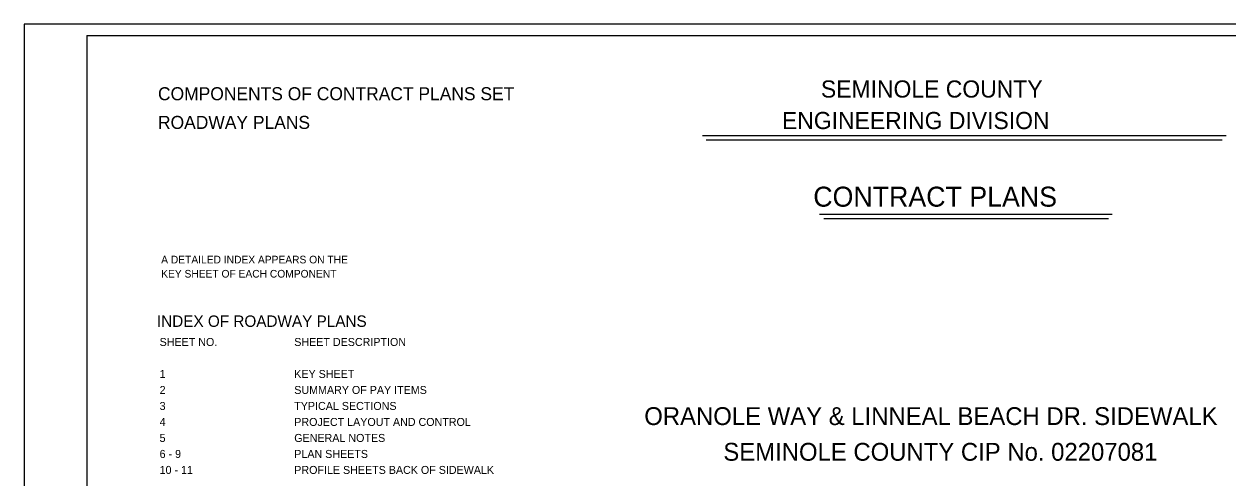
# Model space of a CAD drawing. Extents: x 2157516 to 2331756, y 2153820 to 2265756.
# Drawn here: x 2157516 to 2268726, y 2223812 to 2265756 of the extents above; entities that cross this region are included whole.
import ezdxf

# ---------------------------------------------------------------- set-up
doc = ezdxf.new("R2010")
doc.units = 0
for name, color, linetype in [('Default', 7, 'Continuous'), ('PlotBorder_dp', 7, 'Continuous'), ('SheetBorder_dp', 7, 'Continuous'), ('TextLabel', 7, 'Continuous'), ('TextNotes', 7, 'Continuous'), ('TextTitle', 7, 'Continuous')]:
    doc.layers.add(name, color=color, linetype=linetype)

msp = doc.modelspace()

# ---------------------------------------------------------------- linework, layer by layer
at = {"layer": 'PlotBorder_dp'}
msp.add_lwpolyline([(2157516, 2153820), (2331756, 2153820), (2331756, 2265756), (2157516, 2265756)], close=True, dxfattribs=at)
at = {"layer": 'SheetBorder_dp'}
for q in [(2163324, 2154876), (2325948, 2264700)]:
    msp.add_line((2163324, 2264700), q, dxfattribs=at)
at = {"layer": 'TextTitle'}
for p, q in [((2220174, 2255449), (2268565, 2255449)), ((2220521, 2255048), (2268195, 2255048)), ((2230995, 2248184), (2258045, 2248184)), ((2231411, 2247783), (2257699, 2247783))]:
    msp.add_line(p, q, dxfattribs=at)

# ---------------------------------------------------------------- texts
at = {"layer": 'Default'}
for s, p in [('ORANOLE WAY & LINNEAL BEACH DR. SIDEWALK  ', (2214808, 2228700)), ('SEMINOLE COUNTY CIP No. 02207081', (2222114, 2225400))]:
    msp.add_text(s, height=1649.96, dxfattribs=at).set_placement(p)
at = {"layer": 'TextLabel'}
for s, height, p in [('COMPONENTS OF CONTRACT PLANS SET', 1203.84, (2169888, 2258717)), ('ROADWAY PLANS', 1203.84, (2169888, 2256067)), ('INDEX OF ROADWAY PLANS', 1056, (2169788, 2237772))]:
    msp.add_text(s, height=height, dxfattribs=at).set_placement(p)
at = {"layer": 'TextNotes'}
for s, height, p in [('A DETAILED INDEX APPEARS ON THE ', 707.54, (2170183, 2243637)), ('KEY SHEET OF EACH COMPONENT', 707.54, (2170183, 2242328)), ('SHEET NO.', 739.2, (2170036, 2236008)), ('SHEET DESCRIPTION', 739.2, (2182475, 2236008)), ('1', 739, (2170036, 2233052)), ('KEY SHEET', 739.2, (2182475, 2233052)), ('2', 739, (2170036, 2231573)), ('SUMMARY OF PAY ITEMS ', 739.2, (2182475, 2231573)), ('3', 739, (2170036, 2230095)), ('TYPICAL SECTIONS ', 739.2, (2182475, 2230095)), ('4', 739, (2170036, 2228616)), ('PROJECT LAYOUT AND CONTROL', 739.2, (2182475, 2228616)), ('5', 739, (2170036, 2227138)), ('GENERAL NOTES ', 739.2, (2182475, 2227138)), ('6 - 9', 739.2, (2170036, 2225660)), ('PLAN SHEETS', 739.2, (2182475, 2225660)), ('10 - 11', 739.2, (2170036, 2224181)), ('PROFILE SHEETS BACK OF SIDEWALK', 739.2, (2182475, 2224181))]:
    msp.add_text(s, height=height, dxfattribs=at).set_placement(p)
at = {"layer": 'TextTitle'}
for s, height, p in [('SEMINOLE COUNTY', 1584, (2231127, 2258964)), ('ENGINEERING DIVISION', 1584, (2227530, 2256051)), ('CONTRACT PLANS', 1848, (2230421, 2248881))]:
    msp.add_text(s, height=height, dxfattribs=at).set_placement(p)

doc.saveas('drawing.dxf')
